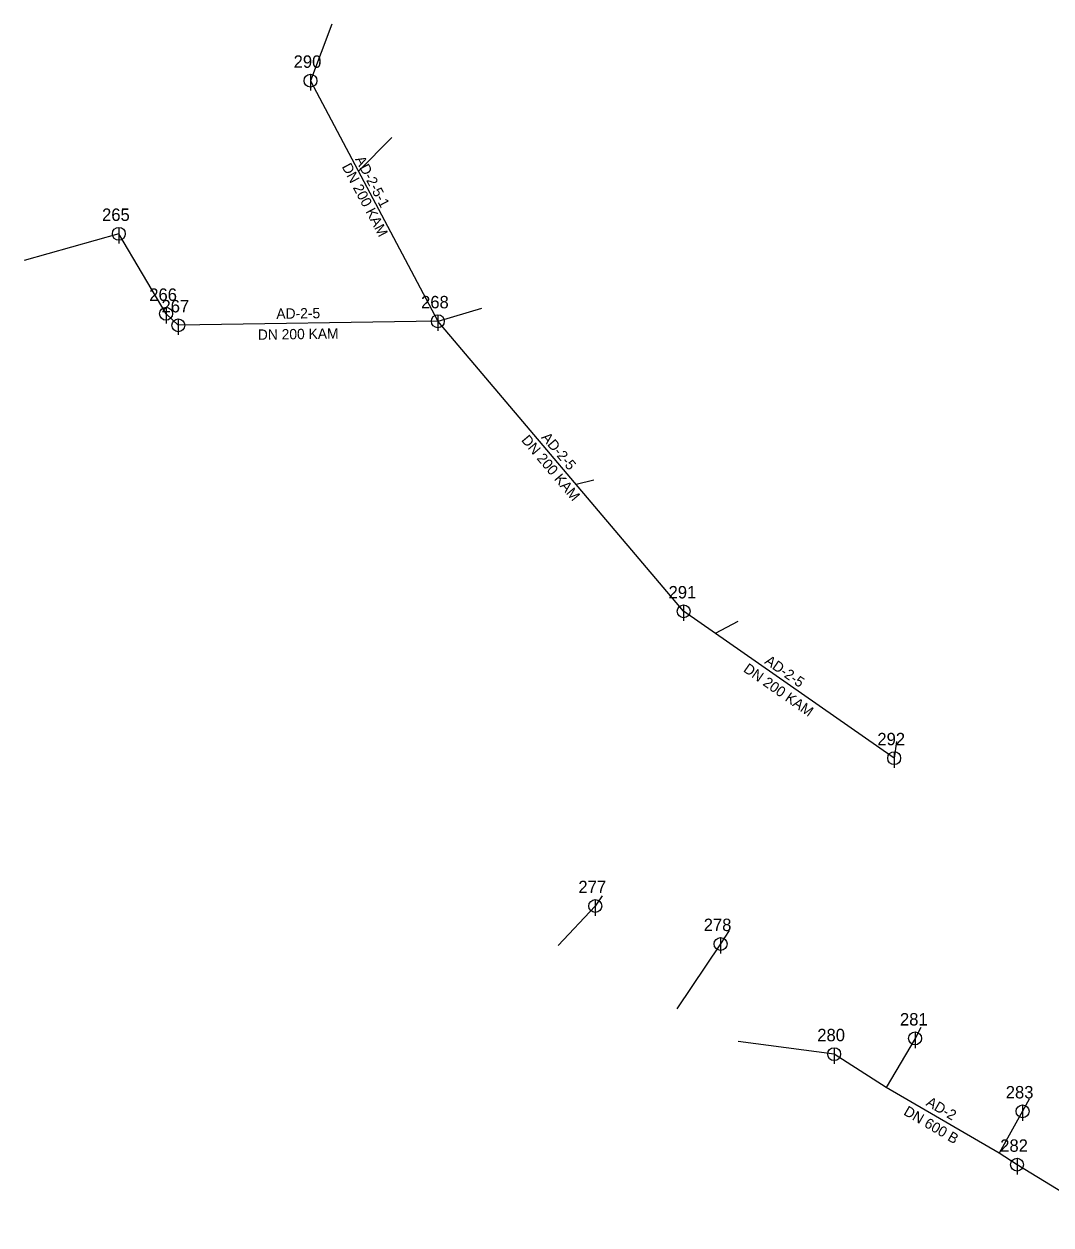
# Model space of a CAD drawing. Extents: x -443519 to -443022, y -1121479 to -1120928.
# Drawn here: x -443433.7 to -443274.4, y -1121320 to -1121133.7 of the extents above; entities that cross this region are included whole.
import ezdxf

# ---------------------------------------------------------------- set-up
doc = ezdxf.new("R2010")
doc.units = 0
for name, color, linetype in [('_pripojka_kanal_jednotna_priblizne_', 7, 'Continuous'), ('_stoka_jednotna_smvak_prevzato_z_dokumentace_', 7, 'Continuous'), ('Default', 7, 'Continuous'), ('MoLevel 119', 7, 'Continuous'), ('MoLevel 120', 7, 'Continuous'), ('MoLevel 68', 7, 'Continuous'), ('MoLevel 69', 7, 'Continuous')]:
    doc.layers.add(name, color=color, linetype=linetype)

# ---------------------------------------------------------------- blocks, each defined once
blk = doc.blocks.new('_sachta_kanal_prevzato_z_dokumentace_')
at = {"layer": 'Default'}
blk.add_line((0, 0.00005), (0, -0.000075), dxfattribs=at)
blk.add_circle((0, 0), 0.00005, dxfattribs=at)

msp = doc.modelspace()

# ---------------------------------------------------------------- linework, layer by layer
at = {"layer": '_pripojka_kanal_jednotna_priblizne_'}
for p, q in [((-443385.98, -1121133.67), (-443389.3, -1121142.46)), ((-443376.66, -1121151.29), (-443381.86, -1121156.5)), ((-443362.75, -1121177.8), (-443369.53, -1121179.8)), ((-443345.34, -1121204.45), (-443348.09, -1121205.08)), ((-443323.02, -1121226.34), (-443326.49, -1121228.2)), ((-443298.38, -1121244.94), (-443298.74, -1121247.55)), ((-443344.06, -1121268.89), (-443345.12, -1121270.49)), ((-443324.33, -1121274.28), (-443325.67, -1121276.37)), ((-443294.59, -1121289.32), (-443295.5, -1121291.02)), ((-443277.81, -1121300.46), (-443278.82, -1121302.33))]:
    msp.add_line(p, q, dxfattribs=at)
at = {"layer": '_stoka_jednotna_smvak_prevzato_z_dokumentace_'}
for p, q in [((-443389.3, -1121142.46), (-443369.53, -1121179.77)), ((-443419.02, -1121166.21), (-443433.74, -1121170.33)), ((-443411.7, -1121178.61), (-443419.02, -1121166.21)), ((-443409.8, -1121180.4), (-443411.7, -1121178.61)), ((-443369.53, -1121179.77), (-443409.8, -1121180.4)), ((-443331.4, -1121224.77), (-443369.53, -1121179.77)), ((-443298.74, -1121247.55), (-443331.4, -1121224.77)), ((-443345.12, -1121270.49), (-443350.89, -1121276.61)), ((-443325.67, -1121276.37), (-443332.44, -1121286.42)), ((-443295.5, -1121291.02), (-443299.97, -1121298.62)), ((-443308.05, -1121293.46), (-443322.96, -1121291.48)), ((-443299.97, -1121298.62), (-443308.05, -1121293.46)), ((-443282.46, -1121308.82), (-443299.97, -1121298.62)), ((-443278.82, -1121302.33), (-443282.46, -1121308.82)), ((-443279.68, -1121310.61), (-443282.46, -1121308.82)), ((-443264.37, -1121319.96), (-443279.68, -1121310.61))]:
    msp.add_line(p, q, dxfattribs=at)

# ---------------------------------------------------------------- block references
at = {"layer": 'MoLevel 119', "xscale": 20000, "yscale": 20000}
for p in [(-443389.3, -1121142.46), (-443419.02, -1121166.21), (-443411.7, -1121178.61), (-443369.53, -1121179.77), (-443409.8, -1121180.4), (-443331.4, -1121224.77), (-443298.74, -1121247.55), (-443345.12, -1121270.49), (-443325.67, -1121276.37), (-443295.5, -1121291.02), (-443308.05, -1121293.46), (-443278.82, -1121302.33), (-443279.68, -1121310.61)]:
    msp.add_blockref('_sachta_kanal_prevzato_z_dokumentace_', p, dxfattribs=at)

# ---------------------------------------------------------------- texts
at = {"layer": 'MoLevel 120'}
for s, p in [('290', (-443391.91, -1121140.46)), ('265', (-443421.63, -1121164.21)), ('266', (-443414.31, -1121176.61)), ('267', (-443412.41, -1121178.4)), ('268', (-443372.14, -1121177.77)), ('291', (-443333.74, -1121222.77)), ('292', (-443301.35, -1121245.55)), ('277', (-443347.73, -1121268.49)), ('278', (-443328.29, -1121274.37)), ('281', (-443297.84, -1121289.02)), ('280', (-443310.67, -1121291.46)), ('283', (-443281.43, -1121300.33)), ('282', (-443282.29, -1121308.61))]:
    msp.add_text(s, height=1.926, dxfattribs=at).set_placement(p)
at = {"layer": 'MoLevel 68'}
for s, rotation, p in [('DN 200 KAM', 297.9124, (-443384.48, -1121155.78)), ('DN 200 KAM', 0.8965, (-443397.45, -1121182.66)), ('DN 200 KAM', 310.2769, (-443356.67, -1121198.26)), ('DN 200 KAM', 325.1037, (-443322.26, -1121234.03)), ('DN 600 B', 329.7845, (-443297.4, -1121302.78))]:
    msp.add_text(s, height=1.605, rotation=rotation, dxfattribs=at).set_placement(p)
at = {"layer": 'MoLevel 69'}
for s, rotation, p in [('AD-2-5-1', 297.9124, (-443382.42, -1121154.64)), ('AD-2-5', 0.8965, (-443394.58, -1121179.41)), ('AD-2-5', 310.2769, (-443353.57, -1121197.84)), ('AD-2-5', 325.1037, (-443318.96, -1121232.78)), ('AD-2', 329.7845, (-443293.92, -1121301.35))]:
    msp.add_text(s, height=1.605, rotation=rotation, dxfattribs=at).set_placement(p)

doc.saveas('drawing.dxf')
